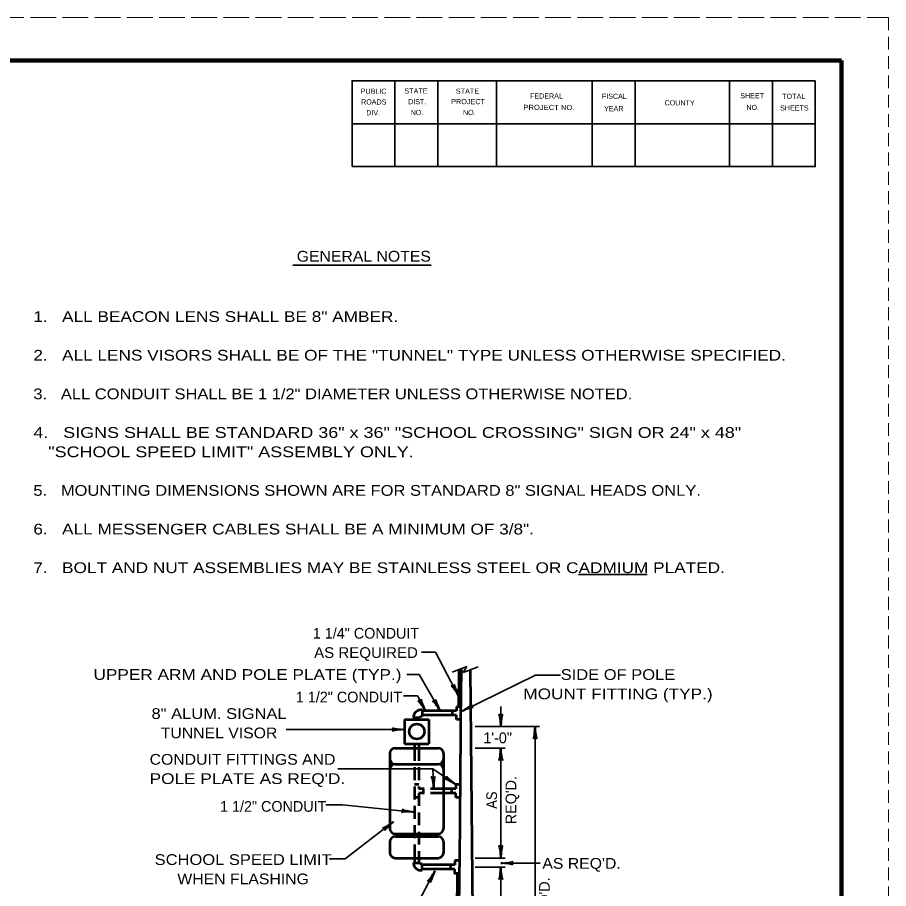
# Model space of a CAD drawing. Extents: x -1 to 679, y 1 to 441.
# Drawn here: x 475.8 to 678.8, y 237.8 to 440.8 of the extents above; entities that cross this region are included whole.
import ezdxf
from ezdxf.enums import TextEntityAlignment as Align

# ---------------------------------------------------------------- set-up
doc = ezdxf.new("R2010")
doc.units = 0
doc.linetypes.add('LONG_DASHED', pattern=[7.5, 6, -1.5])
doc.linetypes.add('MEDIUM_DASHED', pattern=[4.5, 3, -1.5])
doc.layers.add('1', color=7, linetype='Continuous', lineweight=35)
doc.layers.add('61', color=7, linetype='Continuous', lineweight=35)

msp = doc.modelspace()

# ---------------------------------------------------------------- linework, layer by layer
at = {"layer": '1', "linetype": 'MEDIUM_DASHED', "lineweight": 13}
msp.add_line((678.842, 440.796), (678.822, 0.776), dxfattribs=at)
at = {"layer": '1'}
for p, q in [((540.008, 383.055), (572.241, 383.055)), ((606.583, 311.052), (622.548, 311.052)), ((573.207, 292.904), (570.013, 292.904)), ((578.636, 282.666), (573.207, 292.904)), ((577.089, 288.288), (580.584, 289.576)), ((580.584, 289.576), (579.664, 288.196)), ((579.664, 288.196), (583.159, 289.484)), ((579.269, 279.129), (596.556, 287.536)), ((596.556, 287.536), (602.374, 287.536)), ((588.457, 275.571), (588.457, 280.289)), ((538.415, 274.903), (566.042, 274.903)), ((582.457, 275.571), (597.457, 275.571)), ((596.457, 275.571), (596.457, 202.354)), ((582.457, 270.593), (589.457, 270.593)), ((588.457, 270.593), (588.457, 244.968)), ((572.624, 265.721), (572.833, 261.093)), ((582.457, 244.968), (589.457, 244.968)), ((588.461, 243.786), (597.66, 243.786)), ((582.457, 242.825), (589.457, 242.825)), ((588.457, 242.825), (588.457, 202.354))]:
    msp.add_line(p, q, dxfattribs=at)
at = {"layer": '1', "lineweight": 53}
for p, q in [((578.714, 288.887), (578.634, 280.218)), ((579.216, 289.072), (579.105, 277.093)), ((581.334, 288.812), (582.135, 202.343)), ((579.105, 280.218), (578.105, 280.218)), ((578.105, 280.218), (578.105, 279.218)), ((570.103, 279.468), (570.103, 277.968)), ((578.105, 279.218), (570.103, 279.218)), ((578.105, 278.218), (570.103, 278.218)), ((577.105, 279.218), (577.105, 278.218)), ((578.105, 277.218), (578.105, 278.218)), ((566.042, 277.218), (571.667, 277.218)), ((566.042, 277.218), (566.042, 271.593)), ((568.105, 277.718), (569.605, 277.718)), ((568.355, 277.218), (568.355, 277.718)), ((569.355, 277.218), (569.355, 277.718)), ((571.667, 277.218), (571.667, 271.593)), ((579.077, 277.218), (578.105, 277.218)), ((563.855, 270.593), (573.855, 270.593)), ((566.042, 271.593), (571.667, 271.593)), ((568.355, 271.593), (568.355, 270.593)), ((569.355, 271.593), (569.355, 270.593)), ((562.605, 269.343), (562.605, 251.843)), ((575.105, 269.343), (575.105, 251.843)), ((563.855, 266.843), (573.855, 266.843)), ((569.355, 262.093), (568.355, 262.093)), ((578.966, 262.093), (577.966, 262.093)), ((577.966, 262.093), (577.966, 261.093)), ((570.355, 261.093), (570.355, 260.093)), ((577.966, 261.093), (575.105, 261.093)), ((577.966, 260.093), (575.105, 260.093)), ((576.966, 261.093), (576.966, 260.093)), ((577.966, 259.093), (577.966, 260.093)), ((569.355, 259.093), (568.355, 259.093)), ((578.966, 259.093), (577.966, 259.093)), ((563.855, 250.593), (573.855, 250.593)), ((563.855, 249.968), (573.855, 249.968)), ((562.605, 248.718), (562.605, 246.218)), ((575.105, 248.718), (575.105, 246.218)), ((563.855, 244.968), (573.855, 244.968)), ((568.105, 243.852), (569.605, 243.852)), ((568.355, 244.968), (568.355, 243.852)), ((569.355, 244.968), (569.355, 243.852)), ((577.778, 244.352), (577.778, 243.352)), ((578.802, 244.352), (577.778, 244.352)), ((578.802, 244.352), (578.447, 244.352)), ((570.103, 242.102), (570.103, 243.602)), ((577.778, 243.352), (570.103, 243.352)), ((577.778, 242.352), (570.103, 242.352)), ((576.778, 242.352), (576.778, 243.352)), ((578.274, 241.357), (577.913, 202.347))]:
    msp.add_line(p, q, dxfattribs=at)
at = {"layer": '1', "linetype": 'MEDIUM_DASHED', "lineweight": 53}
for p, q in [((568.355, 270.593), (568.355, 244.968)), ((569.355, 270.593), (569.355, 261.093)), ((575.105, 261.093), (569.355, 261.093)), ((575.105, 260.093), (569.355, 260.093)), ((569.355, 260.093), (569.355, 244.968))]:
    msp.add_line(p, q, dxfattribs=at)
at = {"layer": '1'}
for points in [[(566.576, 287.722), (569.434, 287.722), (574.362, 279.218)], [(570.886, 279.218), (569.012, 282.751), (565.819, 282.751)], [(550.503, 265.721), (572.624, 265.721), (577.966, 262.093)], [(568.217, 255.684), (551.567, 257.336), (547.675, 257.336)], [(548.549, 244.778), (552.215, 244.778), (563.472, 253.442)], [(573.112, 241.95), (564.215, 225.174), (561.022, 225.174)]]:
    msp.add_lwpolyline(points, dxfattribs=at)
at = {"layer": '1', "lineweight": 53}
for points in [[(579.105, 277.093), (579.077, 274.093), (578.802, 244.352), (578.774, 241.352), (578.413, 202.343)], [(578.774, 241.352), (577.778, 241.352), (577.778, 242.352)]]:
    msp.add_lwpolyline(points, dxfattribs=at)
msp.add_circle((568.888, 274.434), 1.758, dxfattribs=at)
for centre, radius, start, end in [((569.892, 277.693), 1.787, 83.20694, 179.20989), ((570.008, 277.535), 0.443, 77.63194, 155.64369), ((563.855, 269.343), 1.25, 90, 180), ((573.855, 269.343), 1.25, 0, 90), ((563.855, 268.093), 1.25, 180, 270), ((573.855, 268.093), 1.25, 270, 0), ((563.855, 265.593), 1.25, 90, 180), ((573.855, 265.593), 1.25, 0, 90), ((563.855, 251.843), 1.25, 180, 270), ((573.855, 251.843), 1.25, 270, 0), ((563.855, 248.718), 1.25, 90, 180), ((573.855, 248.718), 1.25, 0, 90), ((563.855, 246.218), 1.25, 180, 270), ((573.855, 246.218), 1.25, 270, 0), ((569.892, 243.877), 1.787, 180.79011, 276.79306), ((570.008, 244.035), 0.443, 204.35631, 282.36806)]:
    msp.add_arc(centre, radius, start, end, dxfattribs=at)
at = {"layer": '1', "lineweight": 40}
for centre, major_axis, ratio, start_param, end_param in [((577.884, 283.512), (0.975, -1.504), 0.122415, 0.8963533, 3.1415927), ((578.301, 283.767), (0.668, -1.634), 0.07063, 3.1407148, 5.41811), ((570.134, 280.064), (0.975, -1.504), 0.122415, 0.8963533, 3.1415927), ((570.551, 280.319), (0.668, -1.634), 0.07063, 3.1407148, 5.41811), ((573.576, 280.024), (1.031, -1.467), 0.122415, 0.8963533, 3.1415927), ((573.983, 280.294), (-0.729, 1.608), 0.07063, 6.2823074, 8.5597026), ((580.129, 279.854), (-1.538, -0.921), 0.122415, 0.8963533, 3.1415927), ((580.369, 279.428), (-1.656, -0.61), 0.07063, 3.1407148, 5.41811), ((588.181, 276.662), (0.156, -1.786), 0.122415, 0.8963533, 3.1415927), ((588.669, 276.692), (-0.176, -1.756), 0.07063, 3.1407148, 5.41811), ((564.951, 274.626), (1.786, 0.156), 0.122415, 0.8963533, 3.1415927), ((564.922, 275.114), (1.756, -0.176), 0.07063, 3.1407148, 5.41811), ((596.245, 274.451), (0.176, 1.756), 0.07063, 3.1407148, 5.41811), ((596.733, 274.48), (-0.156, 1.786), 0.122415, 0.8963533, 3.1415927), ((588.245, 269.473), (0.176, 1.756), 0.07063, 3.1407148, 5.41811), ((588.245, 269.473), (0.176, 1.756), 0.07063, 3.1407148, 5.41811), ((588.733, 269.502), (-0.156, 1.786), 0.122415, 0.8963533, 3.1415927), ((588.733, 269.502), (-0.156, 1.786), 0.122415, 0.8963533, 3.1415927), ((572.508, 262.171), (0.237, -1.777), 0.122415, 0.8963533, 3.1415927), ((572.508, 262.171), (0.237, -1.777), 0.122415, 0.8963533, 3.1415927), ((572.994, 262.222), (-0.096, -1.763), 0.07063, 3.1407148, 5.41811), ((572.994, 262.222), (-0.096, -1.763), 0.07063, 3.1407148, 5.41811), ((577.158, 262.898), (1.354, -1.132), 0.07063, 3.1407148, 5.41811), ((576.908, 262.478), (1.565, -0.874), 0.122415, 0.8963533, 3.1415927), ((567.123, 256.005), (1.731, -0.348), 0.07063, 3.1407148, 5.41811), ((567.123, 256.005), (1.731, -0.348), 0.07063, 3.1407148, 5.41811), ((567.104, 255.517), (1.792, -0.021), 0.122415, 0.8963533, 3.1415927), ((567.104, 255.517), (1.792, -0.021), 0.122415, 0.8963533, 3.1415927), ((562.436, 252.984), (1.51, 0.965), 0.122415, 3.1415927, 5.386832), ((562.711, 252.579), (1.285, 1.211), 0.07063, 0.8650754, 3.1424706), ((588.181, 246.059), (0.156, -1.786), 0.122415, 0.8963533, 3.1415927), ((588.181, 246.059), (0.156, -1.786), 0.122415, 0.8963533, 3.1415927), ((588.669, 246.089), (-0.176, -1.756), 0.07063, 3.1407148, 5.41811), ((588.669, 246.089), (-0.176, -1.756), 0.07063, 3.1407148, 5.41811), ((589.552, 244.063), (-1.786, -0.156), 0.122415, 0.8963533, 3.1415927), ((589.552, 244.063), (-1.786, -0.156), 0.122415, 0.8963533, 3.1415927), ((589.582, 243.575), (-1.756, 0.176), 0.07063, 3.1407148, 5.41811), ((589.582, 243.575), (-1.756, 0.176), 0.07063, 3.1407148, 5.41811), ((572.357, 241.115), (0.975, 1.504), 0.122415, 3.1415927, 5.386832), ((572.357, 241.115), (0.975, 1.504), 0.122415, 3.1415927, 5.386832), ((572.774, 240.861), (0.668, 1.634), 0.07063, 0.8650754, 3.1424706), ((572.774, 240.861), (0.668, 1.634), 0.07063, 0.8650754, 3.1424706), ((588.245, 241.704), (0.176, 1.756), 0.07063, 3.1407148, 5.41811), ((588.245, 241.704), (0.176, 1.756), 0.07063, 3.1407148, 5.41811), ((588.733, 241.733), (-0.156, 1.786), 0.122415, 0.8963533, 3.1415927), ((588.733, 241.733), (-0.156, 1.786), 0.122415, 0.8963533, 3.1415927)]:
    msp.add_ellipse(centre, major_axis=major_axis, ratio=ratio, start_param=start_param, end_param=end_param, dxfattribs=at)
at = {"layer": '61', "linetype": 'LONG_DASHED', "lineweight": 13}
msp.add_line((-1.178, 440.796), (678.842, 440.796), dxfattribs=at)
at = {"layer": '61', "lineweight": 158}
msp.add_line((667.862, 430.796), (667.882, 10.756), dxfattribs=at)
at = {"layer": '61'}
for p, q in [((563.782, 426.036), (563.782, 406.036)), ((573.782, 426.036), (573.782, 406.036)), ((587.462, 426.036), (587.462, 406.036)), ((609.782, 426.036), (609.782, 406.036)), ((619.782, 426.036), (619.782, 406.036)), ((641.762, 426.056), (641.762, 406.056)), ((651.762, 426.056), (651.762, 406.056)), ((661.782, 416.016), (553.762, 416.036))]:
    msp.add_line(p, q, dxfattribs=at)
at = {"layer": '61', "lineweight": 158}
msp.add_lwpolyline([(667.862, 430.796), (28.822, 430.796), (28.822, 10.776)], dxfattribs=at)
at = {"layer": '61'}
for points in [[(661.762, 426.056), (553.782, 426.036), (553.782, 406.036)], [(661.762, 426.056), (661.762, 406.056), (553.782, 406.036)]]:
    msp.add_lwpolyline(points, dxfattribs=at)

# ---------------------------------------------------------------- texts
at = {"layer": '1'}
for s, width, p in [('GENERAL NOTES', 1.1, (540.898, 383.915)), ('1.   ALL BEACON LENS SHALL BE 8" AMBER.', 1.2, (479.512, 369.847)), ('2.   ALL LENS VISORS SHALL BE OF THE "TUNNEL" TYPE UNLESS OTHERWISE SPECIFIED.', 1.2, (479.512, 360.847)), ('3.   ALL CONDUIT SHALL BE 1 1/2" DIAMETER UNLESS OTHERWISE NOTED.', 1.15, (479.512, 351.847)), ('4.   SIGNS SHALL BE STANDARD 36" x 36" "SCHOOL CROSSING" SIGN OR 24" x 48"', 1.25, (479.512, 342.847)), ('   "SCHOOL SPEED LIMIT" ASSEMBLY ONLY.', 1.25, (479.512, 338.347)), ('5.   MOUNTING DIMENSIONS SHOWN ARE FOR STANDARD 8" SIGNAL HEADS ONLY.', 1.15, (479.512, 329.347)), ('6.   ALL MESSENGER CABLES SHALL BE A MINIMUM OF 3/8".', 1.2, (479.512, 320.347)), ('7.   BOLT AND NUT ASSEMBLIES MAY BE STAINLESS STEEL OR CADMIUM PLATED.', 1.2, (479.512, 311.347)), ('UPPER ARM AND POLE PLATE (TYP.)', 1.2, (493.529, 286.463)), ('CONDUIT FITTINGS AND', 1.1, (506.615, 266.705)), ("POLE PLATE AS REQ'D.", 1.2, (506.615, 262.205))]:
    msp.add_text(s, height=2.5, dxfattribs=dict(at, width=width)).set_placement(p)
msp.add_text('1 1/4" CONDUIT', height=2.5, dxfattribs=at).set_placement((557.041, 296.075), align=Align.CENTER)
for s, width, p in [('AS REQUIRED', 1.05, (557.041, 291.575)), ('SIDE OF POLE', 1.15, (615.771, 286.458)), ('MOUNT FITTING (TYP.)', 1.2, (615.771, 281.958)), ('8" ALUM. SIGNAL', 1.15, (522.795, 277.36)), ('TUNNEL VISOR', 1.1, (522.795, 272.86)), ('SCHOOL SPEED LIMIT', 1.15, (528.402, 243.348)), ("AS REQ'D.", 1.1, (607.284, 242.464)), ('WHEN FLASHING', 1.1, (528.402, 238.848))]:
    msp.add_text(s, height=2.5, dxfattribs=dict(at, width=width)).set_placement(p, align=Align.CENTER)
for s, p in [('1 1/2" CONDUIT', (540.694, 281.214)), ('1\'-0"', (584.395, 271.718)), ('1 1/2" CONDUIT', (523.03, 255.741))]:
    msp.add_text(s, height=2.5, dxfattribs=at).set_placement(p)
for p in [(592.08, 258.454), (599.865, 234.844)]:
    msp.add_text("REQ'D.", height=2.5, rotation=90, dxfattribs=at).set_placement(p, align=Align.CENTER)
at = {"layer": '1', "width": 0.9}
msp.add_text('AS', height=2.5, rotation=90, dxfattribs=at).set_placement((587.58, 258.455), align=Align.CENTER)
at = {"layer": '61'}
for s, rotation, p in [('PUBLIC', 0.033, (555.822, 423.016)), ('FEDERAL', 0.007, (595.282, 421.896)), ('FISCAL', 359.942, (612.022, 421.836)), ('SHEET', 0.059, (644.282, 421.956)), ('ROADS', 0.124, (555.902, 420.496)), ('DIST.', 0.056, (566.862, 420.576)), ('COUNTY', 0.069, (626.642, 420.296)), ('SHEETS', 359.959, (653.562, 419.116)), ('DIV.', 359.932, (557.102, 417.996)), ('YEAR', 0.105, (612.542, 418.936))]:
    msp.add_text(s, height=1.201, rotation=rotation, dxfattribs=at).set_placement(p)
for s, rotation, width, p in [('STATE', 0.059, 1.05, (565.982, 423.076)), ('STATE', 0.059, 1.05, (577.982, 423.016)), ('TOTAL', 359.926, 1.05, (654.022, 421.816)), ('PROJECT', 359.908, 1.05, (576.902, 420.596)), ('PROJECT NO.', 359.922, 1.1, (593.742, 419.236)), ('NO.', 359.852, 0.95, (645.702, 419.236)), ('NO.', 359.852, 0.95, (567.442, 418.056)), ('NO.', 0.225, 0.95, (579.642, 418.056))]:
    msp.add_text(s, height=1.201, rotation=rotation, dxfattribs=dict(at, width=width)).set_placement(p)

doc.saveas('drawing.dxf')
